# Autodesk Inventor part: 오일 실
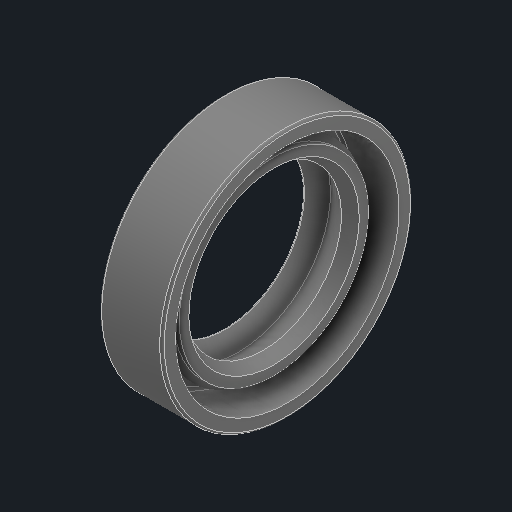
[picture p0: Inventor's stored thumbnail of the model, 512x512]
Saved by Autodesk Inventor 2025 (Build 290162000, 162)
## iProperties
Created: 2025-08
Part Number: 오일 실
Material: 고무
Description: 오일-실
Document SubType Name: Modeling
Designer: infra08
Density: 0.93 g/cm^3
Appearance: 기본값
Author: jhkim
Sending System: Autodesk Inventor 2026
Preprocessor: ST-DEVELOPER v20.1
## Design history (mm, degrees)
feature "Solid1"
node "솔리드1"
